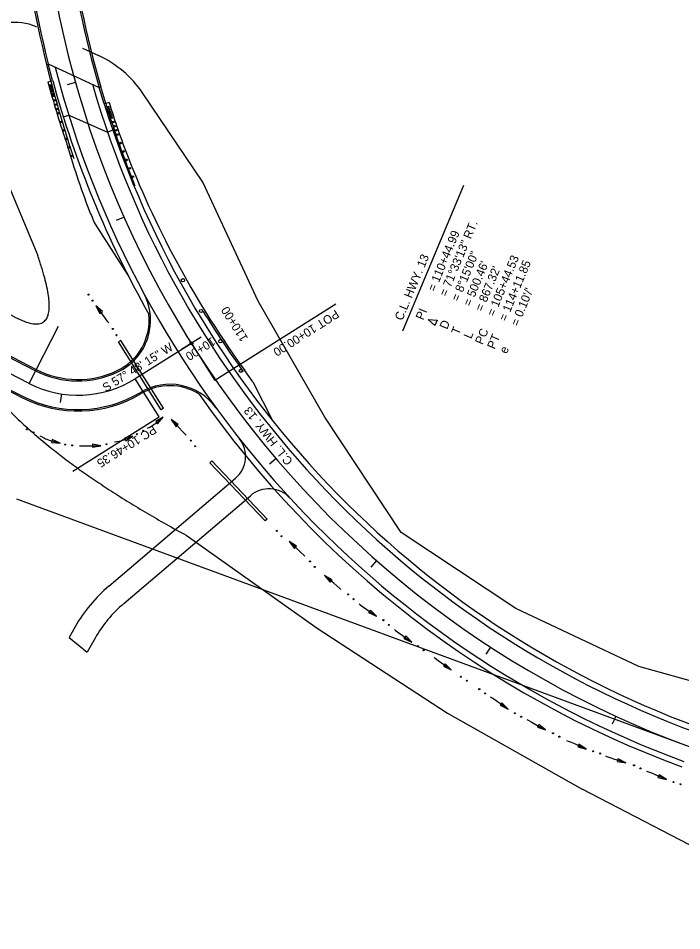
# Model space of a CAD drawing. Extents: x 1384823 to 1386442, y 1973842 to 1975611.
# Drawn here: x 1385177 to 1385640, y 1974088 to 1974725 of the extents above; entities that cross this region are included whole.
import ezdxf

# ---------------------------------------------------------------- set-up
doc = ezdxf.new("R2010")
doc.units = 0
for name, color, linetype in [('B-Super-Deck', 7, 'Continuous'), ('Default', 7, 'Continuous'), ('Level 6', 7, 'Continuous'), ('R_Bridge', 7, 'Continuous'), ('R_Draft', 7, 'Continuous'), ('R_Drainage', 7, 'Continuous'), ('R_Driveway', 7, 'Continuous'), ('R_Guardrail', 7, 'Continuous'), ('R_Horz Alg', 7, 'Continuous'), ('R_Horz Alg Annot', 7, 'Continuous'), ('R_Horz Alg Stationing', 7, 'Continuous'), ('R_Proposed Const Limits', 7, 'Continuous'), ('R_Proposed Road', 7, 'Continuous'), ('R_Shld', 7, 'Continuous'), ('R_Special Ditch', 7, 'Continuous'), ('X_ALI_SURVEY_ML_LABELS', 7, 'Continuous')]:
    doc.layers.add(name, color=color, linetype=linetype)

msp = doc.modelspace()

# ---------------------------------------------------------------- linework, layer by layer
at = {"layer": 'B-Super-Deck'}
for p, q in [((1385201.02, 1974681.17), (1385198.06, 1974692.8)), ((1385199.89, 1974680.88), (1385196.93, 1974692.51)), ((1385199.89, 1974680.88), (1385201.02, 1974681.17)), ((1385237.03, 1974664.91), (1385233.65, 1974676.42)), ((1385238.15, 1974665.24), (1385234.77, 1974676.75)), ((1385238.15, 1974665.24), (1385237.03, 1974664.91))]:
    msp.add_line(p, q, dxfattribs=at)
at = {"layer": 'Level 6'}
msp.add_line((1385445.65, 1974506.46), (1385488.17, 1974608.27), dxfattribs=at)
msp.add_lwpolyline([(1385468.05, 1974510.24), (1385463.3, 1974514.38), (1385469.55, 1974513.86), (1385468.04, 1974510.24)], dxfattribs=at)
at = {"layer": 'R_Bridge'}
for p, q in [((1385196.93, 1974692.51), (1385198.06, 1974692.8)), ((1385198.06, 1974692.8), (1385233.65, 1974676.42)), ((1385234.77, 1974676.75), (1385233.65, 1974676.42))]:
    msp.add_line(p, q, dxfattribs=at)
for radius, start, end in [(710.7, 185.51145, 194.27436), (709.49, 185.51145, 194.27436), (679.49, 186.94136, 196.35314), (678.29, 186.94136, 196.35314)]:
    msp.add_arc((1385885.65, 1974867.74), radius, start, end, dxfattribs=at)
at = {"layer": 'R_Drainage'}
for p, q in [((1385248.67, 1974499.76), (1385246.98, 1974498.7)), ((1385276.82, 1974451.31), (1385246.98, 1974498.7)), ((1385278.51, 1974452.37), (1385248.67, 1974499.76)), ((1385278.51, 1974452.37), (1385276.82, 1974451.31)), ((1385310.9, 1974414.26), (1385312.35, 1974415.64)), ((1385310.9, 1974414.26), (1385349.48, 1974373.67)), ((1385312.35, 1974415.64), (1385350.93, 1974375.05)), ((1385350.93, 1974375.05), (1385349.48, 1974373.67))]:
    msp.add_line(p, q, dxfattribs=at)
at = {"layer": 'R_Driveway'}
for p, q in [((1384943.3, 1974604.13), (1385189.21, 1974478.58)), ((1384934.21, 1974586.31), (1385180.12, 1974460.77)), ((1385240.4, 1974328.21), (1385328.76, 1974403.53)), ((1385250.78, 1974316.03), (1385339.14, 1974391.35)), ((1385216.85, 1974299.87), (1385212.54, 1974292.38)), ((1385212.54, 1974292.38), (1385225.13, 1974282.17)), ((1385230.72, 1974291.89), (1385225.13, 1974282.17))]:
    msp.add_line(p, q, dxfattribs=at)
for centre, radius, start, end in [((1385229.49, 1974513.89), 40, 295.39716, 28.33665), ((1385218.77, 1974536.47), 65, 242.95416, 295.39716), ((1385218.77, 1974536.47), 85, 242.95416, 300.83269), ((1385282.83, 1974429.14), 40, 36.03885, 120.83269), ((1385315.78, 1974418.75), 20, 310.44589, 38.23404), ((1385352.11, 1974376.13), 20, 42.65773, 130.44589), ((1385310.47, 1974246.02), 108, 130.44589, 150.09036), ((1385310.47, 1974246.02), 92, 130.44589, 150.09036)]:
    msp.add_arc(centre, radius, start, end, dxfattribs=at)
at = {"layer": 'R_Guardrail'}
for points in [[(1385199.13, 1974677.31), (1385198.87, 1974678.26), (1385199.82, 1974678.52), (1385200.09, 1974677.57)], [(1385199.55, 1974675.8), (1385199.28, 1974676.75), (1385200.24, 1974677.02), (1385200.5, 1974676.07)], [(1385199.97, 1974674.3), (1385199.7, 1974675.25), (1385200.65, 1974675.52), (1385200.92, 1974674.56)], [(1385200.39, 1974672.79), (1385200.12, 1974673.74), (1385201.07, 1974674.01), (1385201.34, 1974673.06)], [(1385200.8, 1974671.28), (1385200.54, 1974672.24), (1385201.49, 1974672.51), (1385201.76, 1974671.55)], [(1385201.22, 1974669.78), (1385200.95, 1974670.73), (1385201.91, 1974671), (1385202.17, 1974670.05)], [(1385202.05, 1974666.77), (1385201.79, 1974667.72), (1385202.75, 1974667.98), (1385203.01, 1974667.03)], [(1385202.89, 1974663.76), (1385202.63, 1974664.71), (1385203.58, 1974664.97), (1385203.84, 1974664.02)], [(1385203.72, 1974660.75), (1385203.46, 1974661.7), (1385204.42, 1974661.96), (1385204.68, 1974661.01)], [(1385239.53, 1974662.1), (1385239.21, 1974663.03), (1385240.15, 1974663.35), (1385240.47, 1974662.41)], [(1385240.02, 1974660.62), (1385239.71, 1974661.55), (1385240.64, 1974661.87), (1385240.96, 1974660.93)], [(1385204.56, 1974657.74), (1385204.3, 1974658.69), (1385205.25, 1974658.95), (1385205.51, 1974658)], [(1385240.52, 1974659.13), (1385240.2, 1974660.07), (1385241.14, 1974660.39), (1385241.46, 1974659.45)], [(1385241.02, 1974657.65), (1385240.7, 1974658.59), (1385241.64, 1974658.91), (1385241.95, 1974657.97)], [(1385241.51, 1974656.17), (1385241.19, 1974657.11), (1385242.13, 1974657.43), (1385242.45, 1974656.49)], [(1385242.01, 1974654.69), (1385241.69, 1974655.63), (1385242.63, 1974655.94), (1385242.95, 1974655.01)], [(1385206.3, 1974651.71), (1385206, 1974652.66), (1385206.95, 1974652.95), (1385207.24, 1974652.01)], [(1385243, 1974651.73), (1385242.69, 1974652.67), (1385243.63, 1974652.98), (1385243.94, 1974652.04)], [(1385243.99, 1974648.76), (1385243.68, 1974649.7), (1385244.62, 1974650.01), (1385244.93, 1974649.08)], [(1385208.18, 1974645.75), (1385207.88, 1974646.7), (1385208.83, 1974646.99), (1385209.12, 1974646.05)], [(1385244.98, 1974645.8), (1385244.67, 1974646.74), (1385245.61, 1974647.05), (1385245.92, 1974646.11)], [(1385245.97, 1974642.84), (1385245.66, 1974643.78), (1385246.6, 1974644.09), (1385246.92, 1974643.15)], [(1385210.06, 1974639.79), (1385209.77, 1974640.74), (1385210.71, 1974641.03), (1385211.01, 1974640.09)], [(1385248.03, 1974636.92), (1385247.69, 1974637.84), (1385248.62, 1974638.19), (1385248.96, 1974637.26)], [(1385211.94, 1974633.83), (1385211.65, 1974634.78), (1385212.59, 1974635.07), (1385212.89, 1974634.13)], [(1385213.82, 1974627.87), (1385213.53, 1974628.82), (1385214.47, 1974629.11), (1385214.77, 1974628.17)], [(1385250.22, 1974631.06), (1385249.88, 1974631.99), (1385250.81, 1974632.34), (1385251.15, 1974631.41)], [(1385252.42, 1974625.21), (1385252.07, 1974626.14), (1385253, 1974626.48), (1385253.34, 1974625.56)], [(1385254.61, 1974619.36), (1385254.26, 1974620.29), (1385255.19, 1974620.63), (1385255.54, 1974619.7)], [(1385256.8, 1974613.5), (1385256.46, 1974614.43), (1385257.38, 1974614.78), (1385257.73, 1974613.85)]]:
    msp.add_lwpolyline(points, close=True, dxfattribs=at)
for centre in [(1385292.05, 1974541.78), (1385304.68, 1974520.29), (1385318.16, 1974499.21), (1385332.48, 1974478.51)]:
    msp.add_circle(centre, 1.11, dxfattribs=at)
for centre, radius, start, end in [((1385890.88, 1974856.66), 712.99, 194.27244, 197.86456), ((1385919.55, 1974875.11), 712.99, 197.11877, 202.0197), ((1385889.8, 1974848.46), 709.49, 197.26063, 198.2029), ((1385882.78, 1974875.18), 677.21, 211.6455, 215.89593)]:
    msp.add_arc(centre, radius, start, end, dxfattribs=at)
at = {"layer": 'R_Horz Alg'}
for p, q in [((1385184.66, 1974469.67), (1384860, 1974635.42)), ((1385297.95, 1974497.7), (1385258.73, 1974473.01))]:
    msp.add_line(p, q, dxfattribs=at)
for centre, radius, start, end in [((1385885.65, 1974867.74), 694.49, 178.21827, 249.77203), ((1385218.77, 1974536.47), 75, 242.95416, 302.19589)]:
    msp.add_arc(centre, radius, start, end, dxfattribs=at)
at = {"layer": 'R_Horz Alg Annot'}
for p, q in [((1385398.83, 1974525.07), (1385314.25, 1974471.81)), ((1385184.66, 1974469.67), (1385205.07, 1974509.65)), ((1385298.48, 1974496.86), (1385314.25, 1974471.81)), ((1385275.4, 1974446.52), (1385258.73, 1974473.01)), ((1385215.1, 1974408.56), (1385275.4, 1974446.52)), ((1385175.93, 1974389.11), (1385645.53, 1974216.08))]:
    msp.add_line(p, q, dxfattribs=at)
at = {"layer": 'R_Horz Alg Stationing'}
for p, q in [((1385217.05, 1974679.86), (1385211.28, 1974678.23)), ((1385250.93, 1974585.86), (1385245.45, 1974583.43)), ((1385304.72, 1974501.96), (1385291.18, 1974493.44)), ((1385293.69, 1974504.47), (1385302.21, 1974490.93)), ((1385207.3, 1974462.35), (1385206.39, 1974456.42)), ((1385357.13, 1974417.2), (1385352.56, 1974413.31)), ((1385427.25, 1974346.02), (1385423.29, 1974341.52)), ((1385506.85, 1974285.64), (1385503.58, 1974280.62)), ((1385594.3, 1974237.31), (1385591.78, 1974231.87))]:
    msp.add_line(p, q, dxfattribs=at)
at = {"layer": 'R_Proposed Const Limits'}
for p, q in [((1385189.73, 1974718.65), (1385189.41, 1974718.8)), ((1385221.99, 1974703.8), (1385233.08, 1974698.7))]:
    msp.add_line(p, q, dxfattribs=at)
for points in [[(1385142.82, 1974673.34), (1385190.65, 1974559.09)], [(1386071.91, 1974087.53), (1385982.81, 1974134.96), (1385891.23, 1974175.63), (1385797.15, 1974209.55), (1385703.98, 1974245.91), (1385610.41, 1974272.17), (1385524.42, 1974312.63), (1385444.41, 1974365.55), (1385391.15, 1974446.2), (1385344.58, 1974527.06), (1385306.04, 1974610.34), (1385263.8, 1974672.65)], [(1385294.34, 1974363.68), (1385385.8, 1974298.85), (1385476.8, 1974239.46), (1385570.72, 1974186.3)], [(1385861.7, 1974095.5), (1385763.2, 1974117.41), (1385664.21, 1974138), (1385570.72, 1974186.3)]]:
    msp.add_lwpolyline(points, dxfattribs=at)
for centre, radius, start, end in [((1385175.1, 1974686.86), 35, 65.28339, 202.71839), ((1385201.72, 1974630.57), 75, 34.1304, 65.28339)]:
    msp.add_arc(centre, radius, start, end, dxfattribs=at)
for points in [[(1384947.85, 1974613.03), (1385041.24, 1974607.26), (1385137.89, 1974535.23), (1385212.58, 1974496.45), (1385190.65, 1974559.09)], [(1384927.84, 1974573.84), (1384995.55, 1974512.2), (1385125.46, 1974499.52), (1385208.39, 1974410.41), (1385294.34, 1974363.68)]]:
    msp.add_open_spline(points, degree=2, dxfattribs=at)
at = {"layer": 'R_Proposed Road'}
for p, q in [((1385208.55, 1974655.8), (1385212.37, 1974657)), ((1385212.37, 1974657), (1385239.38, 1974645.26)), ((1385243.15, 1974646.59), (1385239.38, 1974645.26))]:
    msp.add_line(p, q, dxfattribs=at)
for radius, start in [(705.49, 194.53783), (683.49, 196.06158)]:
    msp.add_arc((1385885.65, 1974867.74), radius, start, 249.77203, dxfattribs=at)
at = {"layer": 'R_Shld'}
for p, q in [((1385197.73, 1974680.33), (1385199.89, 1974680.88)), ((1385240.49, 1974665.92), (1385238.15, 1974665.24)), ((1384943.76, 1974605.02), (1385189.66, 1974479.47)), ((1384933.75, 1974585.42), (1385179.66, 1974459.88)), ((1385230.67, 1974581), (1385253.61, 1974545.4)), ((1385340.93, 1974470.94), (1385335.22, 1974478.77)), ((1385340.93, 1974470.94), (1385354.51, 1974443.94))]:
    msp.add_line(p, q, dxfattribs=at)
for centre, radius, start, end in [((1385885.65, 1974867.74), 712.99, 195.23918, 198.68605), ((1385885.65, 1974867.74), 709.49, 195.24346, 209.5184), ((1385885.65, 1974867.74), 679.49, 197.36504, 249.77203), ((1385885.65, 1974867.74), 675.99, 197.37028, 200.80497), ((1385895.79, 1974841.89), 714.86, 196.46276, 200.59128), ((1385882.96, 1974875.33), 676.22, 201.48754, 215.90487), ((1385887.03, 1974868.32), 716.49, 202.81646, 203.64146), ((1385229.49, 1974513.89), 39, 295.39716, 6.30035), ((1385218.77, 1974536.47), 64, 242.95416, 295.39716), ((1385282.83, 1974429.14), 39, 58.07515, 120.83269), ((1385218.77, 1974536.47), 86, 242.95416, 300.83269), ((1385885.65, 1974867.74), 709.49, 214.8571, 249.77203)]:
    msp.add_arc(centre, radius, start, end, dxfattribs=at)
at = {"layer": 'R_Special Ditch'}
for p, q in [((1385231.34, 1974524.02), (1385234.09, 1974518.59)), ((1385235.79, 1974519.85), (1385231.34, 1974524.02)), ((1385234.09, 1974518.59), (1385235.79, 1974519.85)), ((1385278.3, 1974446.22), (1385273.03, 1974443.16)), ((1385274.4, 1974441.54), (1385278.3, 1974446.22)), ((1385283.9, 1974444.59), (1385287.28, 1974439.52)), ((1385288.81, 1974440.98), (1385283.9, 1974444.59)), ((1385273.03, 1974443.16), (1385274.4, 1974441.54)), ((1385287.28, 1974439.52), (1385288.81, 1974440.98)), ((1385257.2, 1974432.98), (1385251.27, 1974431.6)), ((1385251.27, 1974431.6), (1385252.1, 1974429.66)), ((1385252.1, 1974429.66), (1385257.2, 1974432.98)), ((1385200.84, 1974430.61), (1385200.24, 1974428.58)), ((1385200.24, 1974428.58), (1385206.29, 1974427.9)), ((1385206.29, 1974427.9), (1385200.84, 1974430.61)), ((1385234.85, 1974426.23), (1385228.85, 1974427.26)), ((1385228.85, 1974427.26), (1385228.86, 1974425.15)), ((1385228.86, 1974425.15), (1385234.85, 1974426.23)), ((1385366.3, 1974359.33), (1385369.97, 1974354.48)), ((1385371.41, 1974356.03), (1385366.3, 1974359.33)), ((1385369.97, 1974354.48), (1385371.41, 1974356.03)), ((1385390.99, 1974335.71), (1385394.85, 1974331)), ((1385396.23, 1974332.6), (1385390.99, 1974335.71)), ((1385394.85, 1974331), (1385396.23, 1974332.6)), ((1385422.95, 1974311.43), (1385421.72, 1974309.7)), ((1385427.23, 1974307.1), (1385422.95, 1974311.43)), ((1385421.72, 1974309.7), (1385427.23, 1974307.1)), ((1385447.6, 1974293.42), (1385446.38, 1974291.69)), ((1385446.38, 1974291.69), (1385451.88, 1974289.09)), ((1385451.88, 1974289.09), (1385447.6, 1974293.42)), ((1385475.16, 1974274.01), (1385473.94, 1974272.29)), ((1385473.94, 1974272.29), (1385479.45, 1974269.68)), ((1385479.45, 1974269.68), (1385475.16, 1974274.01)), ((1385514.78, 1974246.74), (1385513.55, 1974245.02)), ((1385519.03, 1974242.37), (1385514.78, 1974246.74)), ((1385513.55, 1974245.02), (1385519.03, 1974242.37)), ((1385540.56, 1974231.61), (1385539.52, 1974229.77)), ((1385539.52, 1974229.77), (1385545.26, 1974227.73)), ((1385545.26, 1974227.73), (1385540.56, 1974231.61)), ((1385568.58, 1974217.89), (1385567.7, 1974215.96)), ((1385567.7, 1974215.96), (1385573.59, 1974214.42)), ((1385573.59, 1974214.42), (1385568.58, 1974217.89)), ((1385595.97, 1974207.69), (1385595.3, 1974205.68)), ((1385595.3, 1974205.68), (1385601.33, 1974204.8)), ((1385601.33, 1974204.8), (1385595.97, 1974207.69)), ((1385624.57, 1974196.52), (1385623.69, 1974194.6)), ((1385629.58, 1974193.06), (1385624.57, 1974196.52)), ((1385623.69, 1974194.6), (1385629.58, 1974193.06))]:
    msp.add_line(p, q, dxfattribs=at)
for points in [[(1385240.3, 1974511.99), (1385239.67, 1974512.84), (1385238.01, 1974515.09), (1385236.35, 1974517.33), (1385234.68, 1974519.57), (1385233, 1974521.8), (1385231.34, 1974524.02)], [(1385294.23, 1974433.71), (1385293.5, 1974434.48), (1385291.59, 1974436.51), (1385289.67, 1974438.54), (1385287.75, 1974440.56), (1385285.82, 1974442.58), (1385283.9, 1974444.58)], [(1385192.12, 1974433.19), (1385193.32, 1974432.59), (1385195.3, 1974431.47), (1385196.17, 1974431.08), (1385197.04, 1974430.78), (1385198.73, 1974430.07), (1385201.13, 1974429.46), (1385206.28, 1974427.91)], [(1385219.85, 1974426.21), (1385220.91, 1974426.21), (1385223.7, 1974426.2), (1385226.49, 1974426.2), (1385229.28, 1974426.21), (1385232.08, 1974426.22), (1385234.85, 1974426.24)], [(1385377.26, 1974349.09), (1385376.49, 1974349.82), (1385374.46, 1974351.73), (1385372.42, 1974353.64), (1385370.38, 1974355.54), (1385368.33, 1974357.45), (1385366.29, 1974359.33)], [(1385402.33, 1974325.89), (1385401.54, 1974326.59), (1385399.43, 1974328.42), (1385397.32, 1974330.25), (1385395.21, 1974332.08), (1385393.1, 1974333.9), (1385390.99, 1974335.71)], [(1385415.02, 1974315.81), (1385415.87, 1974315.19), (1385418.14, 1974313.56), (1385420.41, 1974311.94), (1385422.69, 1974310.32), (1385424.97, 1974308.71), (1385427.24, 1974307.11)], [(1385439.67, 1974297.79), (1385440.52, 1974297.17), (1385442.79, 1974295.55), (1385445.06, 1974293.92), (1385447.34, 1974292.31), (1385449.62, 1974290.69), (1385451.89, 1974289.09)], [(1385467.23, 1974278.39), (1385468.09, 1974277.77), (1385470.36, 1974276.14), (1385472.63, 1974274.52), (1385474.9, 1974272.9), (1385477.18, 1974271.29), (1385479.45, 1974269.69)], [(1385506.69, 1974250.88), (1385507.87, 1974250.23), (1385509.79, 1974249.02), (1385511.74, 1974247.62), (1385513.79, 1974246.14), (1385515.85, 1974244.67), (1385517.9, 1974243.19), (1385519.03, 1974242.37)], [(1385532.23, 1974235.16), (1385533.15, 1974234.64), (1385535.57, 1974233.24), (1385537.99, 1974231.86), (1385540.42, 1974230.48), (1385542.85, 1974229.1), (1385545.26, 1974227.74)], [(1385559.84, 1974220.39), (1385561.12, 1974219.98), (1385563.24, 1974219.17), (1385565.42, 1974218.17), (1385567.72, 1974217.12), (1385570.02, 1974216.06), (1385572.32, 1974215.01), (1385573.59, 1974214.42)], [(1385587.11, 1974209.57), (1385588.11, 1974209.23), (1385590.76, 1974208.33), (1385593.4, 1974207.44), (1385596.05, 1974206.55), (1385598.7, 1974205.67), (1385601.33, 1974204.8)], [(1385615.83, 1974199.02), (1385617.11, 1974198.61), (1385619.23, 1974197.8), (1385621.41, 1974196.8), (1385623.71, 1974195.75), (1385626.01, 1974194.7), (1385628.31, 1974193.64), (1385629.58, 1974193.06)]]:
    msp.add_lwpolyline(points, dxfattribs=at)
for centre in [(1385226.19, 1974531.72), (1385226.19, 1974531.72), (1385228.97, 1974527.55), (1385228.97, 1974527.55), (1385243.11, 1974507.74), (1385243.11, 1974507.74), (1385245.66, 1974503.43), (1385245.66, 1974503.43), (1385183.15, 1974437.69), (1385187.63, 1974435.45), (1385259.89, 1974434.29), (1385264.31, 1974436.66), (1385209.78, 1974427.02), (1385209.78, 1974427.02), (1385214.76, 1974426.49), (1385214.76, 1974426.49), (1385238.78, 1974427.28), (1385297.52, 1974429.82), (1385297.52, 1974429.82), (1385300.56, 1974425.84), (1385300.56, 1974425.84), (1385357.66, 1974366.8), (1385360.94, 1974363.01), (1385380.78, 1974345.41), (1385384.05, 1974341.62), (1385407.36, 1974322.4), (1385411.11, 1974319.08), (1385432.01, 1974304.39), (1385435.76, 1974301.07), (1385456.01, 1974286.25), (1385456.01, 1974286.25), (1385460.13, 1974283.4), (1385460.13, 1974283.4), (1385486.09, 1974264.89), (1385486.09, 1974264.89), (1385490.24, 1974262.09), (1385490.24, 1974262.09), (1385498.99, 1974256.21), (1385498.99, 1974256.21), (1385503.05, 1974253.28), (1385503.05, 1974253.28), (1385523.86, 1974239.43), (1385523.86, 1974239.43), (1385528.24, 1974237), (1385528.24, 1974237), (1385550.46, 1974225.47), (1385550.46, 1974225.47), (1385554.84, 1974223.05), (1385554.84, 1974223.05), (1385578.56, 1974212.86), (1385578.56, 1974212.86), (1385583.33, 1974211.32), (1385583.33, 1974211.32), (1385607.01, 1974203.03), (1385607.01, 1974203.03), (1385611.56, 1974200.94), (1385611.56, 1974200.94), (1385634.65, 1974191.36), (1385634.65, 1974191.36), (1385639.42, 1974189.83), (1385639.42, 1974189.83)]:
    msp.add_circle(centre, 0.375, dxfattribs=at)
for centre, radius, start, end in [((1385242.83, 1974483.87), 51.72, 298.41129, 313.27715), ((1385238.52, 1974469.6), 41.11, 278.10052, 297.01685)]:
    msp.add_arc(centre, radius, start, end, dxfattribs=at)
at = {"layer": 'X_ALI_SURVEY_ML_LABELS'}
msp.add_circle((1385297.95, 1974497.7), 1, dxfattribs=at)

# ---------------------------------------------------------------- texts
at = {"layer": 'Default'}
msp.add_text('S 57%%d 48\' 15" W', height=6, rotation=32.19589, dxfattribs=at).set_placement((1385238.23, 1974463.53))
at = {"layer": 'Level 6'}
for s, height, p in [('= 71%%D33\'13" RT.', 6.0001, (1385476.3, 1974529.98)), ('= 110+44.99', 6.0001, (1385468.1, 1974533.41)), ('C.L. HWY. 13', 6.0001, (1385445.2, 1974513.15)), ('= 8%%D15\'00"', 6.0001, (1385484.63, 1974526.51)), ('= 105+44.53', 6.0001, (1385509.52, 1974516.11)), ("= 500.46'", 6, (1385492.97, 1974523.08)), ('= 114+11.85', 6.0001, (1385517.84, 1974512.63)), ("= 867.32'", 6, (1385501.27, 1974519.55)), ("= 0.10'/'", 6, (1385526.17, 1974509.16)), ('PI', 6, (1385459.8, 1974513.55)), ('D', 6, (1385476.51, 1974507.06)), ('T', 6, (1385484.67, 1974503.22)), ('PC', 6, (1385501.28, 1974496.37)), ('L', 6, (1385493.31, 1974500.48)), ('PT', 6, (1385509.72, 1974493.19)), ('e', 6, (1385518.17, 1974490.01))]:
    msp.add_text(s, height=height, rotation=67.33333, dxfattribs=at).set_placement(p)
at = {"layer": 'R_Draft'}
msp.add_text('C.L. HWY. 13', height=6, rotation=128.15679, dxfattribs=at).set_placement((1385369.1, 1974415.52))
at = {"layer": 'R_Horz Alg Annot'}
for s, rotation, p in [('POT 10+00.00', 212.57114, (1385398.63, 1974521.52)), ('PC 10+46.35', 212.1159, (1385271.18, 1974440.72))]:
    msp.add_text(s, height=6, rotation=rotation, dxfattribs=at).set_placement(p)
at = {"layer": 'R_Horz Alg Stationing'}
for s, rotation, p in [('110+00', 122.19589, (1385337.76, 1974501.27)), ('10+00', 212.19589, (1385312.31, 1974502.37))]:
    msp.add_text(s, height=6, rotation=rotation, dxfattribs=at).set_placement(p)

doc.saveas('drawing.dxf')
